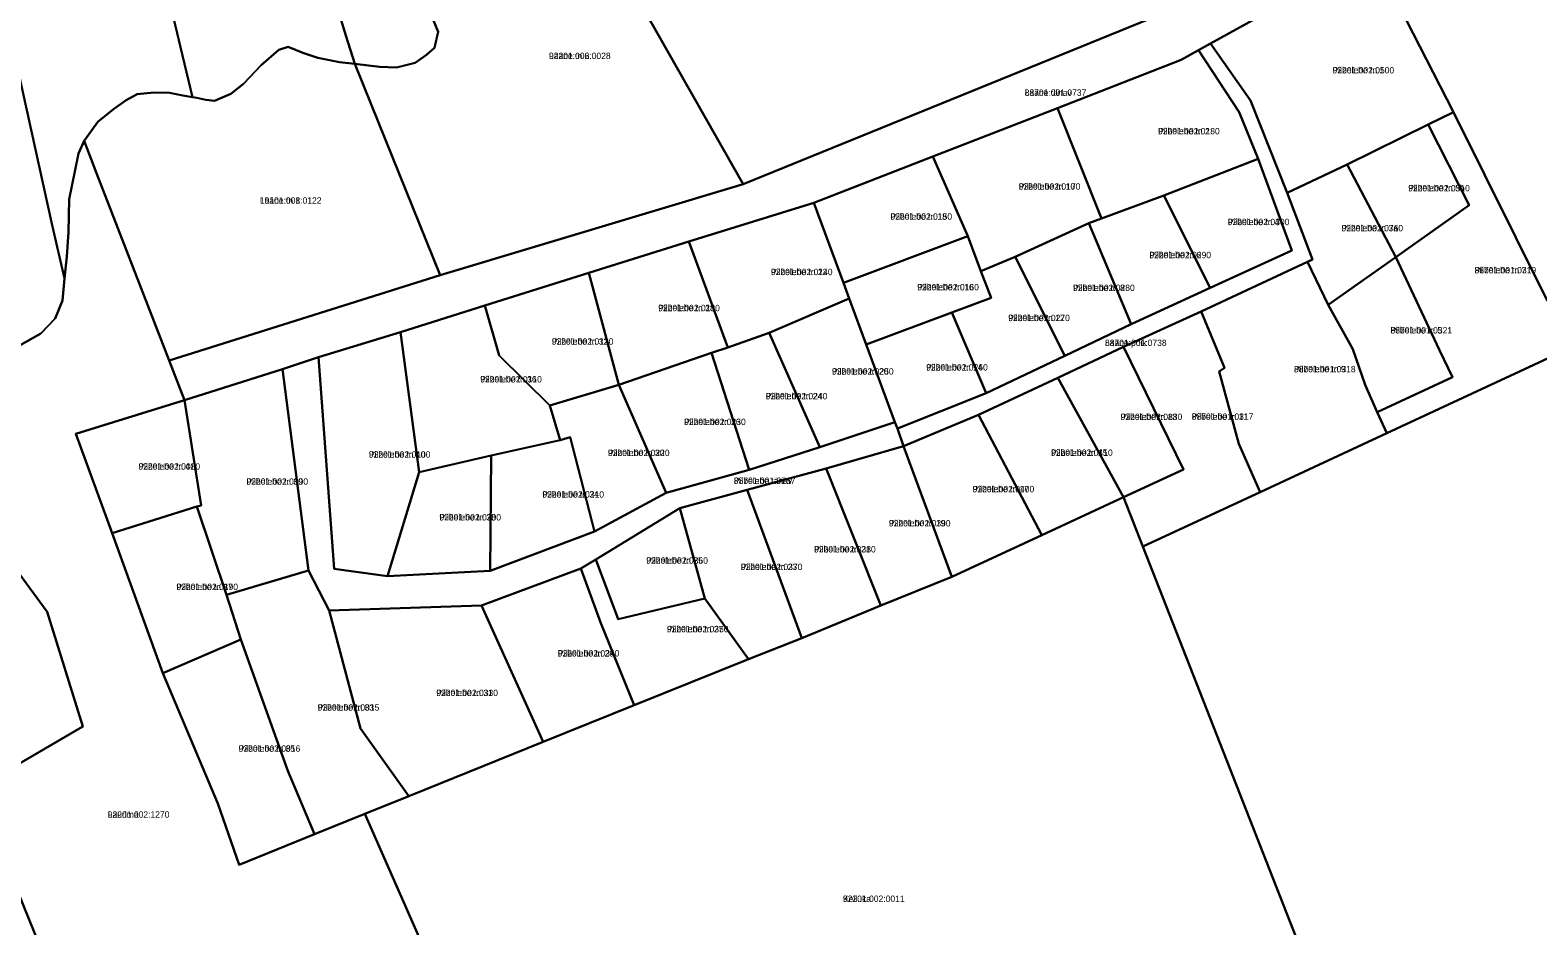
# Model space of a CAD drawing. Extents: x 601493 to 643081, y 6584980 to 6634019.
# Drawn here: x 610753.7 to 611108.4, y 6605427.7 to 6605638.6 of the extents above; entities that cross this region are included whole.
import ezdxf

# ---------------------------------------------------------------- set-up
doc = ezdxf.new("R2010")
doc.units = 0
for name, color, linetype in [('L_AADRESS', 7, 'Continuous'), ('PIIR', 7, 'Continuous'), ('TUNNUS', 7, 'Continuous')]:
    doc.layers.add(name, color=color, linetype=linetype)

msp = doc.modelspace()

# ---------------------------------------------------------------- linework, layer by layer
at = {"layer": 'PIIR'}
for points in [[(610736.95, 6605601.41), (610727.06, 6605631.76), (610721.77, 6605654.74), (610713.75, 6605683.91), (610736.92, 6605690.82), (610743.83, 6605660.73), (610758.89, 6605592.68), (610761.75, 6605580.09), (610761.33, 6605574.93), (610759.58, 6605570.71), (610756.17, 6605567.2), (610746.6, 6605561.79), (610745, 6605568.53)], [(610827.98, 6605637.29), (610815.87, 6605676.82), (610821.71, 6605678.56), (610820.37, 6605683.04), (610819.62, 6605685.54), (610831.47, 6605689.31), (610841.35, 6605661.65), (610845.58, 6605649.22), (610846.92, 6605644.86), (610847.99, 6605642.32), (610848.61, 6605640.85), (610849.7, 6605638.18), (610848.85, 6605634.42), (610846.91, 6605632.73), (610844.24, 6605630.91), (610839.88, 6605629.75), (610835.85, 6605629.92), (610830.05, 6605630.64)], [(611088.53, 6605619.27), (611069.45, 6605656.52), (611067.2, 6605660.57), (611087.22, 6605671.62), (611115.5, 6605682.98), (611151.71, 6605688.75), (611168.49, 6605687.07), (611218.29, 6605624.68), (611110.62, 6605574.97)], [(610781.67, 6605665.57), (610815.87, 6605676.82), (610827.98, 6605637.29), (610830.05, 6605630.64), (610826.46, 6605631.07), (610821.35, 6605632.06), (610817.81, 6605633.21), (610814.35, 6605634.61), (610812.2, 6605633.94), (610808.01, 6605630.33), (610803.9, 6605625.96), (610800.93, 6605623.58), (610797.06, 6605621.93), (610794.99, 6605622.18), (610792.88, 6605622.67), (610791.88, 6605622.82), (610789.07, 6605634.6)], [(610743.83, 6605660.73), (610779.86, 6605673.07), (610781.67, 6605665.57), (610789.07, 6605634.6), (610791.88, 6605622.82), (610789.57, 6605623.17), (610786.44, 6605623.82), (610782.81, 6605623.91), (610778.86, 6605623.49), (610776.31, 6605622.06), (610773.28, 6605620), (610769.64, 6605616.96), (610766.36, 6605612.48), (610765.03, 6605609.57), (610764.18, 6605605.32), (610762.84, 6605598.77), (610762.72, 6605591), (610762.35, 6605585.3), (610761.75, 6605580.09), (610758.89, 6605592.68)], [(611069.45, 6605656.52), (611088.53, 6605619.27), (611082.6, 6605616.38), (611063.53, 6605606.97), (611049.4, 6605600.24), (611040.82, 6605621.98), (611031.37, 6605635.42)], [(610957.71, 6605544.79), (610978.6, 6605553.12), (610997.07, 6605561.95), (611012.68, 6605569.37), (611031.29, 6605577.94), (611050.48, 6605586.74), (611042.58, 6605608.26), (611038.13, 6605619.27), (611028.56, 6605633.82), (611031.37, 6605635.42), (611040.82, 6605621.98), (611049.4, 6605600.24), (611055.39, 6605584.57), (611054.19, 6605584.02), (611029.2, 6605572.36), (611010.87, 6605564.01), (610995.46, 6605556.75), (610976.82, 6605548.04), (610959.16, 6605540.64)], [(610766.36, 6605612.48), (610769.64, 6605616.96), (610773.28, 6605620), (610776.31, 6605622.06), (610778.86, 6605623.49), (610782.81, 6605623.91), (610786.44, 6605623.82), (610789.57, 6605623.17), (610791.88, 6605622.82), (610792.88, 6605622.67), (610794.99, 6605622.18), (610797.06, 6605621.93), (610800.93, 6605623.58), (610803.9, 6605625.96), (610808.01, 6605630.33), (610812.2, 6605633.94), (610814.35, 6605634.61), (610817.81, 6605633.21), (610821.35, 6605632.06), (610826.46, 6605631.07), (610830.05, 6605630.64), (610833.99, 6605620.9), (610850.15, 6605580.93), (610786.38, 6605560.85), (610769.33, 6605604.89)], [(611024.47, 6605631.55), (611028.56, 6605633.82), (611038.13, 6605619.27), (611042.58, 6605608.26), (611020.4, 6605599.67), (611005.76, 6605594.26), (610995.36, 6605620.2)], [(610995.36, 6605620.2), (611005.76, 6605594.26), (611002.73, 6605593.14), (610985.41, 6605585.24), (610977.31, 6605581.86), (610974.32, 6605590.04), (610966.05, 6605608.81)], [(611085.22, 6605563.22), (611074.98, 6605585.16), (611092.24, 6605597.34), (611082.6, 6605616.38), (611088.53, 6605619.27), (611110.62, 6605574.97), (611116.37, 6605563.97), (611072.84, 6605543.74), (611070.61, 6605548.64), (611088.32, 6605556.9)], [(611082.6, 6605616.38), (611092.24, 6605597.34), (611074.98, 6605585.16), (611063.53, 6605606.97)], [(610966.05, 6605608.81), (610974.32, 6605590.04), (610945.07, 6605579.07), (610938.08, 6605597.9)], [(611042.58, 6605608.26), (611050.48, 6605586.74), (611031.29, 6605577.94), (611020.4, 6605599.67)], [(611054.19, 6605584.02), (611055.39, 6605584.57), (611049.4, 6605600.24), (611063.53, 6605606.97), (611074.98, 6605585.16), (611059.09, 6605573.9)], [(611005.76, 6605594.26), (611020.4, 6605599.67), (611031.29, 6605577.94), (611012.68, 6605569.37), (611002.73, 6605593.14)], [(610938.08, 6605597.9), (610945.07, 6605579.07), (610946.38, 6605575.38), (610927.56, 6605567.3), (610917.8, 6605563.9), (610908.61, 6605588.8)], [(611002.73, 6605593.14), (611012.68, 6605569.37), (610997.07, 6605561.95), (610985.41, 6605585.24)], [(610908.61, 6605588.8), (610917.8, 6605563.9), (610914.01, 6605562.59), (610892.19, 6605555.1), (610885.09, 6605581.43)], [(610974.32, 6605590.04), (610977.31, 6605581.86), (610979.78, 6605575.58), (610970.5, 6605572.11), (610950.37, 6605564.6), (610946.38, 6605575.38), (610945.07, 6605579.07)], [(610979.78, 6605575.58), (610977.31, 6605581.86), (610985.41, 6605585.24), (610997.07, 6605561.95), (610978.6, 6605553.12), (610970.5, 6605572.11)], [(611064.83, 6605563.52), (611059.09, 6605573.9), (611074.98, 6605585.16), (611085.22, 6605563.22), (611088.32, 6605556.9), (611070.61, 6605548.64), (611067.75, 6605555.09)], [(611034.66, 6605559.05), (611029.2, 6605572.36), (611054.19, 6605584.02), (611059.09, 6605573.9), (611064.83, 6605563.52), (611067.75, 6605555.09), (611070.61, 6605548.64), (611072.84, 6605543.74), (611043.06, 6605529.83), (611038.05, 6605541.19), (611033.39, 6605558.23)], [(610885.09, 6605581.43), (610892.19, 6605555.1), (610875.94, 6605550.23), (610864.04, 6605561.97), (610860.63, 6605573.77)], [(610946.38, 6605575.38), (610950.37, 6605564.6), (610957.1, 6605546.29), (610939.49, 6605540.41), (610927.56, 6605567.3)], [(610860.63, 6605573.77), (610864.04, 6605561.97), (610875.94, 6605550.23), (610878.36, 6605542.09), (610862.15, 6605538.43), (610845.23, 6605534.54), (610840.79, 6605567.48)], [(610970.5, 6605572.11), (610978.6, 6605553.12), (610957.71, 6605544.79), (610957.1, 6605546.29), (610950.37, 6605564.6)], [(611024.99, 6605535.13), (611010.87, 6605564.01), (611029.2, 6605572.36), (611034.66, 6605559.05), (611033.39, 6605558.23), (611038.05, 6605541.19), (611043.06, 6605529.83), (611015.47, 6605517.02), (611010.92, 6605528.62)], [(610840.79, 6605567.48), (610845.23, 6605534.54), (610837.78, 6605510.07), (610825.22, 6605511.78), (610821.51, 6605561.58)], [(610917.8, 6605563.9), (610927.56, 6605567.3), (610939.49, 6605540.41), (610922.88, 6605535.1), (610914.01, 6605562.59)], [(610995.46, 6605556.75), (611010.87, 6605564.01), (611024.99, 6605535.13), (611010.92, 6605528.62)], [(610813.07, 6605558.78), (610821.51, 6605561.58), (610825.22, 6605511.78), (610837.78, 6605510.07), (610861.92, 6605511.3), (610886.45, 6605520.59), (610903.3, 6605529.7), (610922.88, 6605535.1), (610939.49, 6605540.41), (610957.1, 6605546.29), (610957.71, 6605544.79), (610959.16, 6605540.64), (610940.94, 6605535.37), (610922.39, 6605530.34), (610906.51, 6605526.04), (610886.74, 6605514.01), (610883.25, 6605511.85), (610859.85, 6605503.12), (610824.07, 6605501.96), (610819.14, 6605511.38)], [(610914.01, 6605562.59), (610922.88, 6605535.1), (610903.3, 6605529.7), (610892.19, 6605555.1)], [(610813.07, 6605558.78), (610819.14, 6605511.38), (610799.89, 6605505.65), (610792.93, 6605526.43), (610793.94, 6605526.72), (610790.01, 6605551.49)], [(610892.19, 6605555.1), (610903.3, 6605529.7), (610886.45, 6605520.59), (610880.7, 6605542.8), (610878.36, 6605542.09), (610875.94, 6605550.23)], [(610995.46, 6605556.75), (611010.92, 6605528.62), (610991.67, 6605519.71), (610976.82, 6605548.04)], [(610790.01, 6605551.49), (610793.94, 6605526.72), (610792.93, 6605526.43), (610772.97, 6605520.16), (610764.41, 6605543.58)], [(610976.82, 6605548.04), (610991.67, 6605519.71), (610970.51, 6605509.86), (610959.16, 6605540.64)], [(610878.36, 6605542.09), (610880.7, 6605542.8), (610886.45, 6605520.59), (610861.92, 6605511.3), (610862.15, 6605538.43)], [(610959.16, 6605540.64), (610970.51, 6605509.86), (610953.82, 6605503.11), (610940.94, 6605535.37)], [(610862.15, 6605538.43), (610861.92, 6605511.3), (610837.78, 6605510.07), (610845.23, 6605534.54)], [(610708.65, 6605509.22), (610734.86, 6605532.72), (610757.66, 6605501.65), (610766.06, 6605474.64), (610740.89, 6605460.03), (610726.14, 6605449.82), (610705.06, 6605487.47)], [(610940.94, 6605535.37), (610953.82, 6605503.11), (610935.23, 6605495.49), (610922.39, 6605530.34)], [(610883.4, 6605338.15), (610832.44, 6605454.09), (610842.77, 6605458.25), (610874.41, 6605471.08), (610895.77, 6605479.69), (610922.7, 6605490.51), (610935.23, 6605495.49), (610953.82, 6605503.11), (610970.51, 6605509.86), (610991.67, 6605519.71), (611010.92, 6605528.62), (611015.47, 6605517.02), (611057.99, 6605408.6), (610948.86, 6605366.75), (610901.13, 6605343.14)], [(610922.39, 6605530.34), (610935.23, 6605495.49), (610922.7, 6605490.51), (610912.45, 6605504.78), (610906.51, 6605526.04)], [(610792.93, 6605526.43), (610799.89, 6605505.65), (610803.22, 6605495.14), (610784.87, 6605487.26), (610772.97, 6605520.16)], [(610906.51, 6605526.04), (610912.45, 6605504.78), (610892.03, 6605499.94), (610886.74, 6605514.01)], [(610799.89, 6605505.65), (610819.14, 6605511.37), (610824.07, 6605501.96), (610831.43, 6605474.23), (610842.77, 6605458.25), (610832.44, 6605454.09), (610820.62, 6605449.32), (610814.32, 6605464.22), (610803.22, 6605495.14)], [(610883.25, 6605511.85), (610887.96, 6605498.96), (610895.77, 6605479.69), (610874.41, 6605471.08), (610859.85, 6605503.12)], [(610886.74, 6605514.01), (610892.03, 6605499.94), (610912.45, 6605504.78), (610922.7, 6605490.51), (610895.77, 6605479.69), (610887.96, 6605498.96), (610883.25, 6605511.85)], [(610859.85, 6605503.12), (610874.41, 6605471.08), (610842.77, 6605458.25), (610831.43, 6605474.23), (610824.07, 6605501.98)], [(610784.87, 6605487.26), (610803.22, 6605495.14), (610814.32, 6605464.22), (610820.62, 6605449.32), (610802.87, 6605442.14), (610797.85, 6605456.52)]]:
    msp.add_lwpolyline(points, close=True, dxfattribs=at)
for points in [[(611115.5, 6605682.98), (611087.22, 6605671.62), (611067.2, 6605660.57), (611069.45, 6605656.52), (611031.37, 6605635.42), (611028.56, 6605633.82), (611024.47, 6605631.55), (610995.36, 6605620.2), (610966.05, 6605608.81), (610938.08, 6605597.9), (610908.61, 6605588.8), (610885.09, 6605581.43), (610860.63, 6605573.77), (610840.79, 6605567.48), (610821.51, 6605561.58), (610813.07, 6605558.78), (610790.01, 6605551.49), (610786.38, 6605560.85), (610850.15, 6605580.93), (610921.45, 6605602.34), (611024.03, 6605644.08), (611084.63, 6605677.04), (611113.89, 6605688.79)], [(610890.82, 6605656.18), (610921.45, 6605602.34), (610850.15, 6605580.93), (610833.99, 6605620.9), (610830.05, 6605630.64), (610835.85, 6605629.92), (610839.88, 6605629.75), (610844.24, 6605630.91), (610846.91, 6605632.73), (610848.85, 6605634.42), (610849.7, 6605638.18), (610848.61, 6605640.85)], [(611024.03, 6605644.08), (610921.45, 6605602.34), (610890.82, 6605656.18)], [(610746.6, 6605561.79), (610756.17, 6605567.2), (610759.58, 6605570.71), (610761.33, 6605574.93), (610761.75, 6605580.09), (610762.35, 6605585.3), (610762.72, 6605591), (610762.84, 6605598.77), (610764.18, 6605605.32), (610765.03, 6605609.57), (610766.36, 6605612.48), (610769.33, 6605604.89), (610786.38, 6605560.85), (610790.01, 6605551.49), (610764.41, 6605543.58), (610772.97, 6605520.16), (610784.87, 6605487.26), (610797.85, 6605456.52), (610802.87, 6605442.14), (610820.62, 6605449.32), (610832.44, 6605454.09), (610883.4, 6605338.15)], [(611111.95, 6605420.23), (611101.11, 6605419.33), (611090.27, 6605417.82), (611083.04, 6605416.48), (611076.14, 6605414.88), (611058.46, 6605407.39), (611057.99, 6605408.6), (611015.47, 6605517.02), (611043.06, 6605529.83), (611072.84, 6605543.74), (611116.37, 6605563.97)], [(610799.13, 6605316.51), (610740.89, 6605460.03), (610766.06, 6605474.64), (610757.66, 6605501.65), (610734.86, 6605532.72)], [(610740.89, 6605460.03), (610799.13, 6605316.51)]]:
    msp.add_lwpolyline(points, dxfattribs=at)

# ---------------------------------------------------------------- texts
at = {"layer": 'L_AADRESS'}
for s, p in [('Lääne tn 6', (610875.75, 6605631.76)), ('Piibelehe tn 1', (611060.09, 6605628.38)), ('Lääne tänav', (610987.66, 6605623.11)), ('Piibelehe tn 2', (611019.04, 6605614.04)), ('Piibelehe tn 10', (610986.26, 6605601.03)), ('Piibelehe tn 3b', (611077.89, 6605600.63)), ('Lääne tn 8', (610807.73, 6605597.73)), ('Piibelehe tn 18', (610956.08, 6605593.94)), ('Piibelehe tn 4', (611035.44, 6605592.67)), ('Piibelehe tn 3a', (611062.19, 6605591.21)), ('Piibelehe tn 6', (611017.01, 6605584.89)), ('Piibelehe tn 22', (610927.96, 6605580.9)), ('Piibelehe tn 7', (611093.49, 6605581.33)), ('Piibelehe tn 16', (610962.39, 6605577.32)), ('Piibelehe tn 8', (610999.04, 6605577.17)), ('Piibelehe tn 28', (610901.45, 6605572.42)), ('Piibelehe tn 12', (610983.79, 6605570.08)), ('Piibelehe tn 5', (611073.71, 6605567.17)), ('Piibelehe tn 32', (610876.41, 6605564.54)), ('Lääne põik', (611006.55, 6605564.22)), ('Piibelehe tn 36', (610859.57, 6605555.64)), ('Piibelehe tn 20', (610942.33, 6605557.5)), ('Piibelehe tn 14', (610964.48, 6605558.45)), ('Piibelehe tn 9', (611051.02, 6605558.04)), ('Piibelehe tn 24', (610926.75, 6605551.68)), ('Piibelehe tn 26', (610907.54, 6605545.62)), ('Piibelehe tn 13', (611010.23, 6605546.8)), ('Piibelehe tn 11', (611026.96, 6605546.85)), ('Piibelehe tn 40', (610833.37, 6605537.94)), ('Piibelehe tn 30', (610889.62, 6605538.32)), ('Piibelehe tn 15', (610993.87, 6605538.37)), ('Piibelehe tn 41', (610779.17, 6605535.13)), ('Piibelehe tn 39', (610804.57, 6605531.57)), ('Piibelehe tänav', (610919.23, 6605531.77)), ('Piibelehe tn 34', (610874.19, 6605528.55)), ('Piibelehe tn 17', (610975.41, 6605529.8)), ('Piibelehe tn 38', (610849.96, 6605523.16)), ('Piibelehe tn 19', (610955.72, 6605521.76)), ('Piibelehe tn 25', (610898.64, 6605512.99)), ('Piibelehe tn 21', (610938.11, 6605515.63)), ('Piibelehe tn 23', (610920.87, 6605511.49)), ('Piibelehe tn 37', (610788.09, 6605506.78)), ('Piibelehe tn 27', (610903.48, 6605496.85)), ('Piibelehe tn 29', (610877.81, 6605491.14)), ('Piibelehe tn 31', (610849.24, 6605481.83)), ('Piibelehe tn 33', (610821.33, 6605478.4)), ('Piibelehe tn 35', (610802.74, 6605468.72)), ('Laurima', (610771.95, 6605453.21)), ('Kelluka', (610944.91, 6605433.38))]:
    msp.add_text(s, height=1.5, dxfattribs=at).set_placement(p)
at = {"layer": 'TUNNUS'}
for s, p in [('92201:002:0028', (610875.75, 6605631.76)), ('92201:002:0500', (611060.09, 6605628.38)), ('88701:001:0737', (610987.66, 6605623.11)), ('92201:002:0180', (611019.04, 6605614.04)), ('92201:002:0170', (610986.26, 6605601.03)), ('92201:002:0510', (611077.89, 6605600.63)), ('19101:001:0122', (610807.73, 6605597.73)), ('92201:002:0150', (610956.08, 6605593.94)), ('92201:002:0300', (611035.44, 6605592.67)), ('92201:002:0760', (611062.19, 6605591.21)), ('92201:002:0290', (611017.01, 6605584.89)), ('92201:002:0140', (610927.96, 6605580.9)), ('88701:001:0319', (611093.49, 6605581.33)), ('92201:002:0160', (610962.39, 6605577.32)), ('92201:002:0280', (610999.04, 6605577.17)), ('92201:002:0130', (610901.45, 6605572.42)), ('92201:002:0270', (610983.79, 6605570.08)), ('88701:001:0321', (611073.71, 6605567.17)), ('92201:002:0120', (610876.41, 6605564.54)), ('88701:001:0738', (611006.55, 6605564.22)), ('92201:002:0110', (610859.57, 6605555.64)), ('92201:002:0250', (610942.33, 6605557.5)), ('92201:002:0260', (610964.48, 6605558.45)), ('88701:001:0318', (611051.02, 6605558.04)), ('92201:002:0240', (610926.75, 6605551.68)), ('92201:002:0230', (610907.54, 6605545.62)), ('92201:002:0880', (611010.23, 6605546.8)), ('88701:001:0317', (611026.96, 6605546.85)), ('92201:002:0100', (610833.37, 6605537.94)), ('92201:002:0220', (610889.62, 6605538.32)), ('92201:002:0410', (610993.87, 6605538.37)), ('92201:002:0080', (610779.17, 6605535.13)), ('92201:002:0090', (610804.57, 6605531.57)), ('88701:001:0767', (610919.23, 6605531.77)), ('92201:002:0210', (610874.19, 6605528.55)), ('92201:002:0400', (610975.41, 6605529.8)), ('92201:002:0200', (610849.96, 6605523.16)), ('92201:002:0390', (610955.72, 6605521.76)), ('92201:002:0360', (610898.64, 6605512.99)), ('92201:002:0380', (610938.11, 6605515.63)), ('92201:002:0370', (610920.87, 6605511.49)), ('92201:002:0190', (610788.09, 6605506.78)), ('92201:002:0350', (610903.48, 6605496.85)), ('92201:002:0340', (610877.81, 6605491.14)), ('92201:002:0330', (610849.24, 6605481.83)), ('92201:002:0015', (610821.33, 6605478.4)), ('92201:002:0016', (610802.74, 6605468.72)), ('92201:002:1270', (610771.95, 6605453.21)), ('92201:002:0011', (610944.91, 6605433.38))]:
    msp.add_text(s, height=1.5, dxfattribs=at).set_placement(p)

doc.saveas('drawing.dxf')
